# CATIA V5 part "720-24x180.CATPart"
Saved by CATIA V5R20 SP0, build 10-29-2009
Part number: 720-24x180
Definition: NONE
Nomenclature: 720-24x180
Source: Unknown
Description: 720-24x180
Bounding box of the stored display mesh (mm): x 0 to 180, y -12 to 12, z -12 to 12
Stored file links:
  C:\Users\Utente\Desktop\IO LAVORO\3D X SITO CF\X SITO\720\720-24x180.CATPart

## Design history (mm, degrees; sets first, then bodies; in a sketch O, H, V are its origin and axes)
Body1 "720-24x180" (main body)
  Solid1: solid without history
